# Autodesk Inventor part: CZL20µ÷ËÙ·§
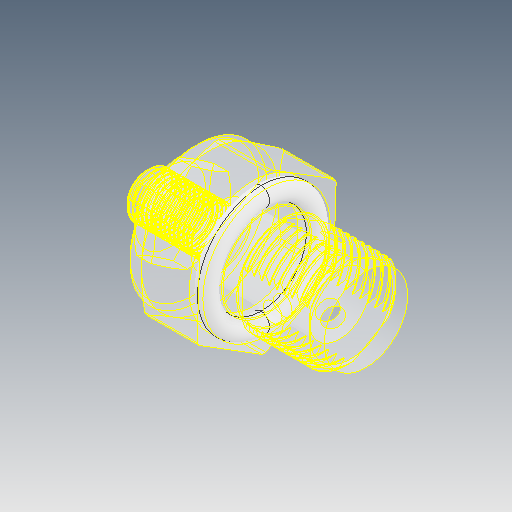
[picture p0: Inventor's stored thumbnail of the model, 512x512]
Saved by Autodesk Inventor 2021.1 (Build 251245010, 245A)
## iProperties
Created: 2021-05
Part Number: CZL20µ÷ËÙ·§
Material: Ogólny
Document SubType Name: Modeling
Designer: user
Density: 1 g/cm^3
Appearance: Domyślna
Author: user
Revision Number: ÈÎºÎ
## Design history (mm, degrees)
feature "NONE"
feature "Złożony1"
node "Bryła1"
body "Srf1"
